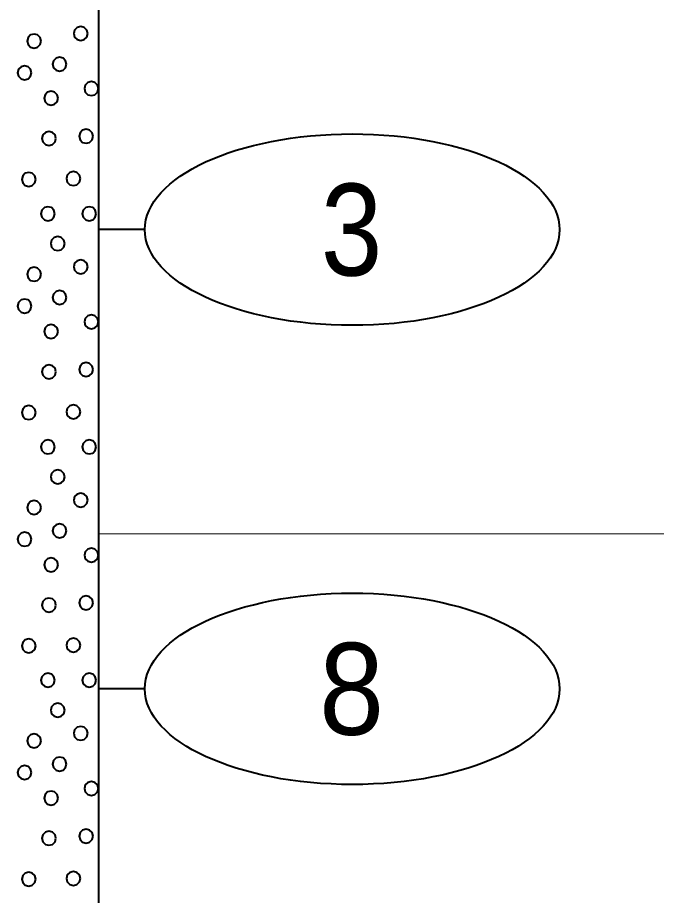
# Model space of a CAD drawing. Extents: x -76 to 974, y -1080 to -735.
# Drawn here: x 418.31 to 425.27, y -946.03 to -936.47 of the extents above; entities that cross this region are included whole.
import ezdxf
from ezdxf.enums import TextEntityAlignment as Align

# ---------------------------------------------------------------- set-up
doc = ezdxf.new("R2010")
doc.units = 0
doc.header["$LTSCALE"] = 0.36
doc.layers.add('27', color=7, linetype='Continuous', lineweight=40)
doc.layers.add('7', color=7, linetype='Continuous', lineweight=13)

msp = doc.modelspace()

# ---------------------------------------------------------------- linework, layer by layer
at = {"layer": '27'}
for p, q in [((419.1974, -946.1789), (419.1974, -936.1789)), ((419.6975, -938.7789), (419.1975, -938.7789)), ((419.6975, -943.7789), (419.1975, -943.7789))]:
    msp.add_line(p, q, dxfattribs=at)
for points in [[(419.0748, -936.6437), (419.0646, -936.6056), (419.0367, -936.5777), (418.9986, -936.5675), (418.9605, -936.5777), (418.9326, -936.6056), (418.9224, -936.6437), (418.9326, -936.6818), (418.9605, -936.7097), (418.9986, -936.7199), (419.0367, -936.7097), (419.0646, -936.6818)], [(418.5676, -936.7251), (418.5574, -936.687), (418.5295, -936.6591), (418.4914, -936.6489), (418.4533, -936.6591), (418.4254, -936.687), (418.4152, -936.7251), (418.4254, -936.7632), (418.4533, -936.7911), (418.4914, -936.8013), (418.5295, -936.7911), (418.5574, -936.7632)], [(418.8447, -936.9781), (418.8345, -936.94), (418.8066, -936.9121), (418.7685, -936.9019), (418.7304, -936.9121), (418.7025, -936.94), (418.6923, -936.9781), (418.7025, -937.0162), (418.7304, -937.0441), (418.7685, -937.0543), (418.8066, -937.0441), (418.8345, -937.0162)], [(418.4633, -937.0709), (418.4531, -937.0328), (418.4252, -937.0049), (418.3871, -936.9947), (418.349, -937.0049), (418.3211, -937.0328), (418.3109, -937.0709), (418.3211, -937.109), (418.349, -937.1369), (418.3871, -937.1471), (418.4252, -937.1369), (418.4531, -937.109)], [(419.1905, -937.2438), (419.1803, -937.2057), (419.1524, -937.1778), (419.1143, -937.1676), (419.0762, -937.1778), (419.0483, -937.2057), (419.0381, -937.2438), (419.0483, -937.2819), (419.0762, -937.3097), (419.1143, -937.32), (419.1524, -937.3097), (419.1803, -937.2819)], [(418.7519, -937.348), (418.7417, -937.3099), (418.7138, -937.282), (418.6757, -937.2718), (418.6376, -937.282), (418.6097, -937.3099), (418.5995, -937.348), (418.6097, -937.3861), (418.6376, -937.414), (418.6757, -937.4242), (418.7138, -937.414), (418.7417, -937.3861)], [(418.729, -937.7866), (418.7188, -937.7485), (418.6909, -937.7206), (418.6528, -937.7104), (418.6147, -937.7206), (418.5868, -937.7485), (418.5766, -937.7866), (418.5868, -937.8247), (418.6147, -937.8526), (418.6528, -937.8628), (418.6909, -937.8526), (418.7188, -937.8247)], [(419.1333, -937.7624), (419.1231, -937.7243), (419.0952, -937.6964), (419.0571, -937.6862), (419.019, -937.6964), (418.9911, -937.7243), (418.9809, -937.7624), (418.9911, -937.8005), (419.019, -937.8284), (419.0571, -937.8386), (419.0952, -937.8284), (419.1231, -937.8005)], [(418.5091, -938.2315), (418.4989, -938.1934), (418.471, -938.1655), (418.4329, -938.1553), (418.3948, -938.1655), (418.3669, -938.1934), (418.3567, -938.2315), (418.3669, -938.2696), (418.3948, -938.2975), (418.4329, -938.3077), (418.471, -938.2975), (418.4989, -938.2696)], [(418.9947, -938.2239), (418.9845, -938.1858), (418.9566, -938.1579), (418.9185, -938.1477), (418.8804, -938.1579), (418.8525, -938.1858), (418.8423, -938.2239), (418.8525, -938.262), (418.8804, -938.2899), (418.9185, -938.3001), (418.9566, -938.2899), (418.9845, -938.262)], [(418.7176, -938.6053), (418.7074, -938.5672), (418.6795, -938.5393), (418.6414, -938.5291), (418.6033, -938.5393), (418.5754, -938.5672), (418.5652, -938.6053), (418.5754, -938.6434), (418.6033, -938.6713), (418.6414, -938.6815), (418.6795, -938.6713), (418.7074, -938.6434)], [(419.1676, -938.6053), (419.1574, -938.5672), (419.1295, -938.5393), (419.0914, -938.5291), (419.0533, -938.5393), (419.0254, -938.5672), (419.0152, -938.6053), (419.0254, -938.6434), (419.0533, -938.6713), (419.0914, -938.6815), (419.1295, -938.6713), (419.1574, -938.6434)], [(418.8239, -938.9316), (418.8137, -938.8935), (418.7858, -938.8656), (418.7477, -938.8554), (418.7096, -938.8656), (418.6818, -938.8935), (418.6715, -938.9316), (418.6818, -938.9697), (418.7096, -938.9976), (418.7477, -939.0078), (418.7858, -938.9976), (418.8137, -938.9697)], [(418.5676, -939.2651), (418.5574, -939.227), (418.5295, -939.1991), (418.4914, -939.1889), (418.4533, -939.1991), (418.4254, -939.227), (418.4152, -939.2651), (418.4254, -939.3032), (418.4533, -939.3311), (418.4914, -939.3413), (418.5295, -939.3311), (418.5574, -939.3032)], [(419.0748, -939.1837), (419.0646, -939.1456), (419.0367, -939.1177), (418.9986, -939.1075), (418.9605, -939.1177), (418.9326, -939.1456), (418.9224, -939.1837), (418.9326, -939.2218), (418.9605, -939.2497), (418.9986, -939.2599), (419.0367, -939.2497), (419.0646, -939.2218)], [(418.8447, -939.5181), (418.8345, -939.48), (418.8066, -939.4521), (418.7685, -939.4419), (418.7304, -939.4521), (418.7025, -939.48), (418.6923, -939.5181), (418.7025, -939.5562), (418.7304, -939.5841), (418.7685, -939.5943), (418.8066, -939.5841), (418.8345, -939.5562)], [(418.4633, -939.6109), (418.4531, -939.5728), (418.4252, -939.5449), (418.3871, -939.5347), (418.349, -939.5449), (418.3211, -939.5728), (418.3109, -939.6109), (418.3211, -939.649), (418.349, -939.6769), (418.3871, -939.6871), (418.4252, -939.6769), (418.4531, -939.649)], [(419.1905, -939.7838), (419.1803, -939.7457), (419.1524, -939.7178), (419.1143, -939.7076), (419.0762, -939.7178), (419.0483, -939.7457), (419.0381, -939.7838), (419.0483, -939.8219), (419.0762, -939.8497), (419.1143, -939.86), (419.1524, -939.8497), (419.1803, -939.8219)], [(418.7519, -939.888), (418.7417, -939.8499), (418.7138, -939.822), (418.6757, -939.8118), (418.6376, -939.822), (418.6097, -939.8499), (418.5995, -939.888), (418.6097, -939.9261), (418.6376, -939.954), (418.6757, -939.9642), (418.7138, -939.954), (418.7417, -939.9261)], [(419.1333, -940.3024), (419.1231, -940.2643), (419.0952, -940.2364), (419.0571, -940.2262), (419.019, -940.2364), (418.9911, -940.2643), (418.9809, -940.3024), (418.9911, -940.3405), (419.019, -940.3684), (419.0571, -940.3786), (419.0952, -940.3684), (419.1231, -940.3405)], [(418.729, -940.3266), (418.7188, -940.2885), (418.6909, -940.2606), (418.6528, -940.2504), (418.6147, -940.2606), (418.5868, -940.2885), (418.5766, -940.3266), (418.5868, -940.3647), (418.6147, -940.3926), (418.6528, -940.4028), (418.6909, -940.3926), (418.7188, -940.3647)], [(418.5091, -940.7715), (418.4989, -940.7334), (418.471, -940.7055), (418.4329, -940.6953), (418.3948, -940.7055), (418.3669, -940.7334), (418.3567, -940.7715), (418.3669, -940.8096), (418.3948, -940.8375), (418.4329, -940.8477), (418.471, -940.8375), (418.4989, -940.8096)], [(418.9947, -940.7639), (418.9845, -940.7258), (418.9566, -940.6979), (418.9185, -940.6877), (418.8804, -940.6979), (418.8525, -940.7258), (418.8423, -940.7639), (418.8525, -940.802), (418.8804, -940.8299), (418.9185, -940.8401), (418.9566, -940.8299), (418.9845, -940.802)], [(418.7176, -941.1453), (418.7074, -941.1072), (418.6795, -941.0793), (418.6414, -941.0691), (418.6033, -941.0793), (418.5754, -941.1072), (418.5652, -941.1453), (418.5754, -941.1834), (418.6033, -941.2113), (418.6414, -941.2215), (418.6795, -941.2113), (418.7074, -941.1834)], [(419.1676, -941.1453), (419.1574, -941.1072), (419.1295, -941.0793), (419.0914, -941.0691), (419.0533, -941.0793), (419.0254, -941.1072), (419.0152, -941.1453), (419.0254, -941.1834), (419.0533, -941.2113), (419.0914, -941.2215), (419.1295, -941.2113), (419.1574, -941.1834)], [(418.8239, -941.4716), (418.8137, -941.4335), (418.7858, -941.4056), (418.7477, -941.3954), (418.7096, -941.4056), (418.6818, -941.4335), (418.6715, -941.4716), (418.6818, -941.5097), (418.7096, -941.5376), (418.7477, -941.5478), (418.7858, -941.5376), (418.8137, -941.5097)], [(419.0748, -941.7237), (419.0646, -941.6856), (419.0367, -941.6577), (418.9986, -941.6475), (418.9605, -941.6577), (418.9326, -941.6856), (418.9224, -941.7237), (418.9326, -941.7618), (418.9605, -941.7897), (418.9986, -941.7999), (419.0367, -941.7897), (419.0646, -941.7618)], [(418.5676, -941.8051), (418.5574, -941.767), (418.5295, -941.7391), (418.4914, -941.7289), (418.4533, -941.7391), (418.4254, -941.767), (418.4152, -941.8051), (418.4254, -941.8432), (418.4533, -941.8711), (418.4914, -941.8813), (418.5295, -941.8711), (418.5574, -941.8432)], [(418.8447, -942.0581), (418.8345, -942.02), (418.8066, -941.9921), (418.7685, -941.9819), (418.7304, -941.9921), (418.7025, -942.02), (418.6923, -942.0581), (418.7025, -942.0962), (418.7304, -942.1241), (418.7685, -942.1343), (418.8066, -942.1241), (418.8345, -942.0962)], [(418.4633, -942.1509), (418.4531, -942.1128), (418.4252, -942.0849), (418.3871, -942.0747), (418.349, -942.0849), (418.3211, -942.1128), (418.3109, -942.1509), (418.3211, -942.189), (418.349, -942.2169), (418.3871, -942.2271), (418.4252, -942.2169), (418.4531, -942.189)], [(419.1905, -942.3238), (419.1803, -942.2857), (419.1524, -942.2578), (419.1143, -942.2476), (419.0762, -942.2578), (419.0483, -942.2857), (419.0381, -942.3238), (419.0483, -942.3619), (419.0762, -942.3897), (419.1143, -942.4), (419.1524, -942.3897), (419.1803, -942.3619)], [(418.7519, -942.428), (418.7417, -942.3899), (418.7138, -942.362), (418.6757, -942.3518), (418.6376, -942.362), (418.6097, -942.3899), (418.5995, -942.428), (418.6097, -942.4661), (418.6376, -942.494), (418.6757, -942.5042), (418.7138, -942.494), (418.7417, -942.4661)], [(418.729, -942.8666), (418.7188, -942.8285), (418.6909, -942.8006), (418.6528, -942.7904), (418.6147, -942.8006), (418.5868, -942.8285), (418.5766, -942.8666), (418.5868, -942.9047), (418.6147, -942.9326), (418.6528, -942.9428), (418.6909, -942.9326), (418.7188, -942.9047)], [(419.1333, -942.8424), (419.1231, -942.8043), (419.0952, -942.7764), (419.0571, -942.7662), (419.019, -942.7764), (418.9911, -942.8043), (418.9809, -942.8424), (418.9911, -942.8805), (419.019, -942.9084), (419.0571, -942.9186), (419.0952, -942.9084), (419.1231, -942.8805)], [(418.5091, -943.3115), (418.4989, -943.2734), (418.471, -943.2455), (418.4329, -943.2353), (418.3948, -943.2455), (418.3669, -943.2734), (418.3567, -943.3115), (418.3669, -943.3496), (418.3948, -943.3775), (418.4329, -943.3877), (418.471, -943.3775), (418.4989, -943.3496)], [(418.9947, -943.3039), (418.9845, -943.2658), (418.9566, -943.2379), (418.9185, -943.2277), (418.8804, -943.2379), (418.8525, -943.2658), (418.8423, -943.3039), (418.8525, -943.342), (418.8804, -943.3699), (418.9185, -943.3801), (418.9566, -943.3699), (418.9845, -943.342)], [(418.7176, -943.6853), (418.7074, -943.6472), (418.6795, -943.6193), (418.6414, -943.6091), (418.6033, -943.6193), (418.5754, -943.6472), (418.5652, -943.6853), (418.5754, -943.7234), (418.6033, -943.7513), (418.6414, -943.7615), (418.6795, -943.7513), (418.7074, -943.7234)], [(419.1676, -943.6853), (419.1574, -943.6472), (419.1295, -943.6193), (419.0914, -943.6091), (419.0533, -943.6193), (419.0254, -943.6472), (419.0152, -943.6853), (419.0254, -943.7234), (419.0533, -943.7513), (419.0914, -943.7615), (419.1295, -943.7513), (419.1574, -943.7234)], [(418.8239, -944.0116), (418.8137, -943.9735), (418.7858, -943.9456), (418.7477, -943.9354), (418.7096, -943.9456), (418.6818, -943.9735), (418.6715, -944.0116), (418.6818, -944.0497), (418.7096, -944.0776), (418.7477, -944.0878), (418.7858, -944.0776), (418.8137, -944.0497)], [(419.0748, -944.2637), (419.0646, -944.2256), (419.0367, -944.1977), (418.9986, -944.1875), (418.9605, -944.1977), (418.9326, -944.2256), (418.9224, -944.2637), (418.9326, -944.3018), (418.9605, -944.3297), (418.9986, -944.3399), (419.0367, -944.3297), (419.0646, -944.3018)], [(418.5676, -944.3451), (418.5574, -944.307), (418.5295, -944.2791), (418.4914, -944.2689), (418.4533, -944.2791), (418.4254, -944.307), (418.4152, -944.3451), (418.4254, -944.3832), (418.4533, -944.4111), (418.4914, -944.4213), (418.5295, -944.4111), (418.5574, -944.3832)], [(418.8447, -944.5981), (418.8345, -944.56), (418.8066, -944.5321), (418.7685, -944.5219), (418.7304, -944.5321), (418.7025, -944.56), (418.6923, -944.5981), (418.7025, -944.6362), (418.7304, -944.6641), (418.7685, -944.6743), (418.8066, -944.6641), (418.8345, -944.6362)], [(418.4633, -944.6909), (418.4531, -944.6528), (418.4252, -944.6249), (418.3871, -944.6147), (418.349, -944.6249), (418.3211, -944.6528), (418.3109, -944.6909), (418.3211, -944.729), (418.349, -944.7569), (418.3871, -944.7671), (418.4252, -944.7569), (418.4531, -944.729)], [(419.1905, -944.8638), (419.1803, -944.8257), (419.1524, -944.7978), (419.1143, -944.7876), (419.0762, -944.7978), (419.0483, -944.8257), (419.0381, -944.8638), (419.0483, -944.9019), (419.0762, -944.9297), (419.1143, -944.94), (419.1524, -944.9297), (419.1803, -944.9019)], [(418.7519, -944.968), (418.7417, -944.9299), (418.7138, -944.902), (418.6757, -944.8918), (418.6376, -944.902), (418.6097, -944.9299), (418.5995, -944.968), (418.6097, -945.0061), (418.6376, -945.034), (418.6757, -945.0442), (418.7138, -945.034), (418.7417, -945.0061)], [(419.1333, -945.3824), (419.1231, -945.3443), (419.0952, -945.3164), (419.0571, -945.3062), (419.019, -945.3164), (418.9911, -945.3443), (418.9809, -945.3824), (418.9911, -945.4205), (419.019, -945.4484), (419.0571, -945.4586), (419.0952, -945.4484), (419.1231, -945.4205)], [(418.729, -945.4066), (418.7188, -945.3685), (418.6909, -945.3406), (418.6528, -945.3304), (418.6147, -945.3406), (418.5868, -945.3685), (418.5766, -945.4066), (418.5868, -945.4447), (418.6147, -945.4726), (418.6528, -945.4828), (418.6909, -945.4726), (418.7188, -945.4447)], [(418.5091, -945.8515), (418.4989, -945.8134), (418.471, -945.7855), (418.4329, -945.7753), (418.3948, -945.7855), (418.3669, -945.8134), (418.3567, -945.8515), (418.3669, -945.8896), (418.3948, -945.9175), (418.4329, -945.9277), (418.471, -945.9175), (418.4989, -945.8896)], [(418.9947, -945.8439), (418.9845, -945.8058), (418.9566, -945.7779), (418.9185, -945.7677), (418.8804, -945.7779), (418.8525, -945.8058), (418.8423, -945.8439), (418.8525, -945.882), (418.8804, -945.9099), (418.9185, -945.9201), (418.9566, -945.9099), (418.9845, -945.882)]]:
    msp.add_lwpolyline(points, close=True, dxfattribs=at)
for centre in [(421.9549, -938.7789), (421.9549, -943.7789)]:
    msp.add_ellipse(centre, major_axis=(2.2574, 0), ratio=0.461538, dxfattribs=at)
at = {"layer": '7'}
msp.add_line((419.1974, -942.09), (459.1974, -942.09), dxfattribs=at)

# ---------------------------------------------------------------- texts
at = {"layer": '27'}
for s, width, p in [('3', 0.9, (421.9478, -939.2788)), ('8', 0.95, (421.9478, -944.2788))]:
    msp.add_text(s, height=1, dxfattribs=dict(at, width=width)).set_placement(p, align=Align.CENTER)

doc.saveas('drawing.dxf')
